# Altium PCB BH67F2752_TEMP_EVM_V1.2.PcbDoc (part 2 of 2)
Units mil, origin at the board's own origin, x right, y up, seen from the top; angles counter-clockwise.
Board outline 4690.02 x 3082.03 mil, 2 copper layers (Top Layer, Bottom Layer); 69 components, 83 nets, 365 pads, 122 vias.
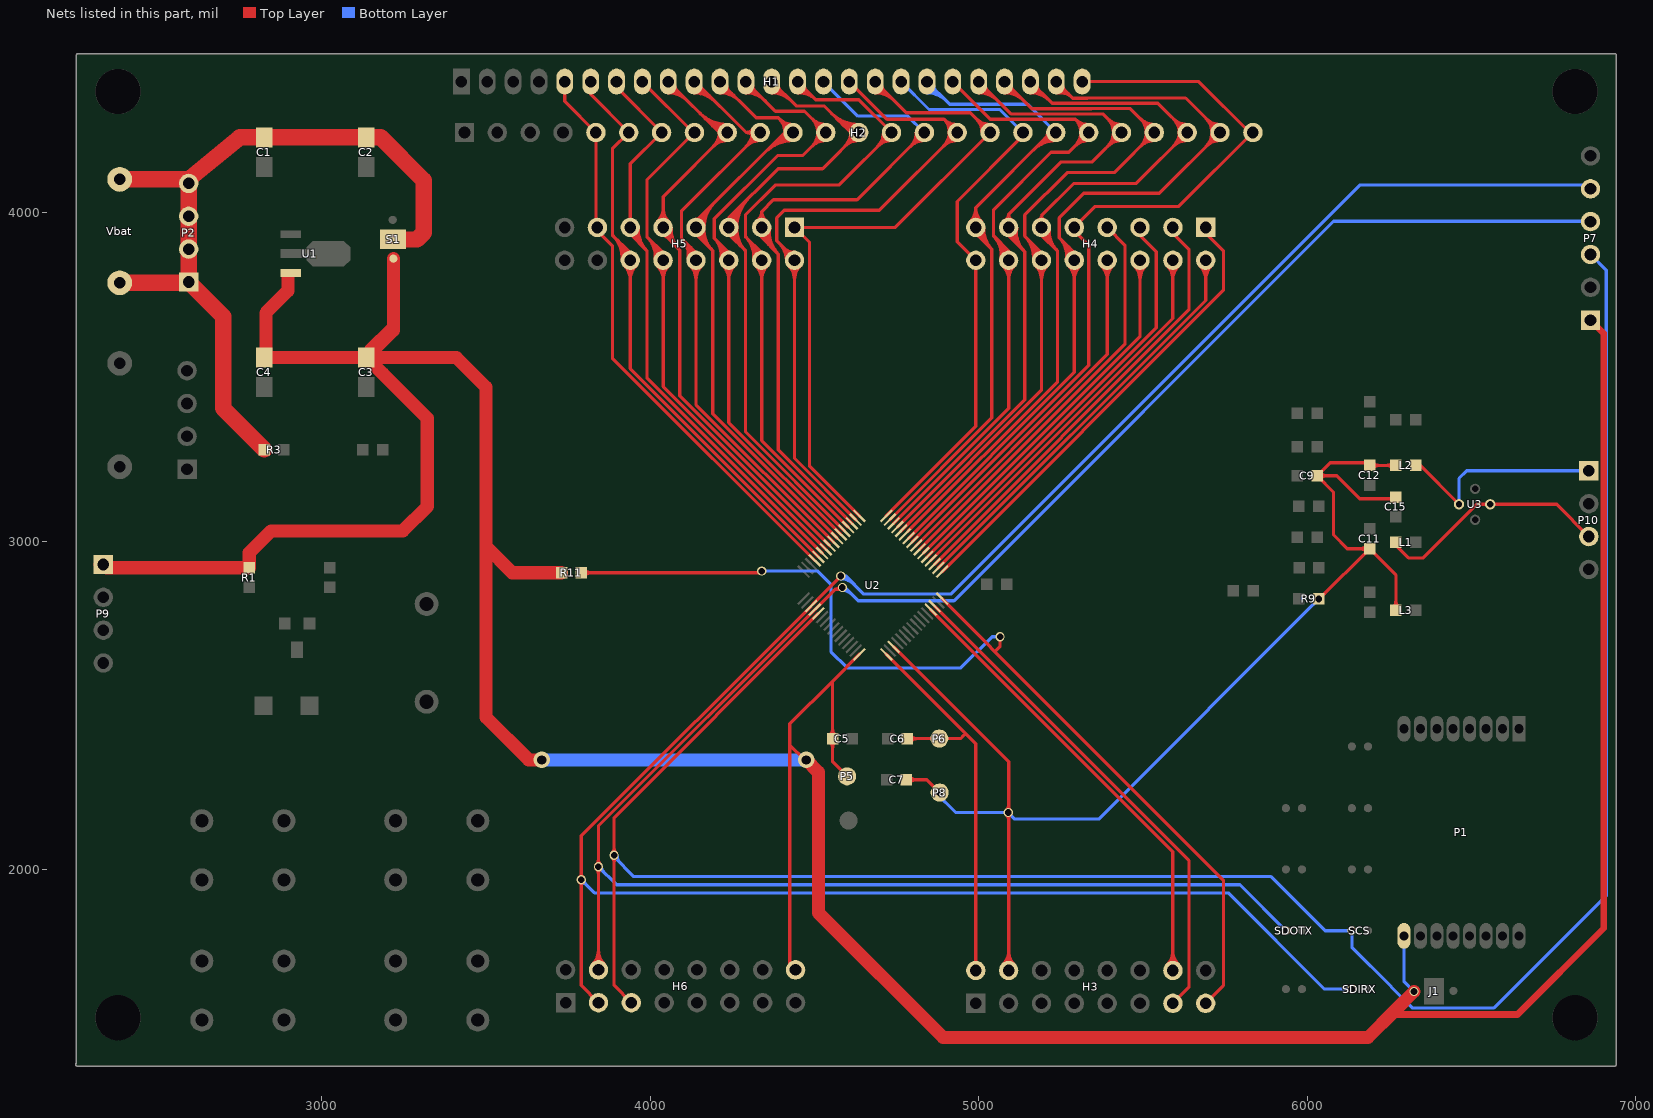
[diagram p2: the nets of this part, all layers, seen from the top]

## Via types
v1: diameter 28, hole 20, Top Layer to Bottom Layer, tented top, 64 vias
v2: diameter 28, hole 16, Top Layer to Bottom Layer, tented top, 56 vias
v3: diameter 50, hole 28, Top Layer to Bottom Layer, tented top, 2 vias

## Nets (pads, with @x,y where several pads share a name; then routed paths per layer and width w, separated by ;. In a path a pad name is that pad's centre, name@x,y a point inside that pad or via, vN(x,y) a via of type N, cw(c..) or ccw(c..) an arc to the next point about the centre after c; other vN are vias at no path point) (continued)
SCSB: H6.5 P7.3 SCS.1 U2.53 | length 6918.2
  Top Layer w10: v1@3883.64,2038.64 cw(c3868.27,2023.27) 3890,2023.27 cw(c3911.73,2023.27) v1@3896.36,2038.64 ; v1@3883.64,2051.36 ccw(c3868.27,2066.73) 3890,2066.73 ccw(c3911.73,2066.73) v1@3896.36,2051.36 ; H6.5@3942.38,1596 3890,1648.37 v1(3890,2045) 3890,2158.86 U2.53@4512.06,2780.92
  Bottom Layer w10: v1(3890,2045) 3890,2040 3950,1980 5890,1980 6054.67,1815.33 v1(6136.05,1815.33) 6136.05,1765 6255,1646.05 6255,1645 6320,1580 6568.71,1580 6910,1921.29 6910,3826.06 P7.3@6862.36,3873.7 ; v1@3899,2045 ccw(c3932.8,2045) 3908.9,2021.1
"SDI RX": H6.3 P7.5 SDIRX.1 U2.51 | length 7143.1
  Top Layer w10: v1@3783.64,1963.64 cw(c3768.27,1948.27) 3790,1948.27 cw(c3811.73,1948.27) v1@3796.36,1963.64 ; v1@3783.64,1976.36 ccw(c3768.27,1991.73) 3790,1991.73 ccw(c3811.73,1991.73) v1@3796.36,1976.36 ; H6.3@3842.38,1596 3790,1648.37 v1(3790,1970) 3790,2104.11 U2.51@4489.43,2803.54 ; U2.51@4494.12,2808.23 4579.94,2894.05 v1(4579.94,2895)
  Bottom Layer w10: v1@3790,1961 cw(c3790,1939.27) 3805.36,1954.64 cw(c3820.73,1970) v1@3799,1970 ; v1(3790,1970) 3830,1930 5760,1930 6052.59,1637.41 v1(6136.05,1637.41) ; v1@4579.94,2886 cw(c4579.94,2827.92) 4621.01,2868.99 ; v1(4579.94,2895) 4595,2895 ; v1@4579.94,2896 cw(c4579.94,2862.06) 4603.94,2886.06 ; v1@4587.87,2890.74 cw(c4595,2886.9) 4595,2895 ; v1@4587.87,2899.26 ccw(c4595,2903.1) 4595,2895 ; P7.5@6867.36,4085 6160,4085 4915,2840 4650,2840 4595,2895
"SDO TX": H6.4 P7.4 SDOTX.1 U2.52 | length 6740
  Top Layer w10: H6.4@3825.03,1713.34 ccw(c3783.16,1755.21) 3842.38,1755.21 ccw(c3901.59,1755.21) H6.4@3859.72,1713.34 ; H6.4@3832.1,1706.27 ccw(c3807.3,1731.07) 3842.38,1731.07 ccw(c3877.45,1731.07) H6.4@3852.65,1706.27 ; v1@3836.01,2003.64 cw(c3820.65,1988.27) 3842.38,1988.27 cw(c3864.1,1988.27) v1@3848.74,2003.64 ; v1@3836.01,2016.36 ccw(c3820.65,2031.73) 3842.38,2031.73 ccw(c3864.1,2031.73) v1@3848.74,2016.36 ; H6.4@3842.38,1696 v1(3842.38,2010) 3842.38,2133.86 U2.52@4500.75,2792.23 4563.52,2855 ; v1@4576.77,2863.63 cw(c4563.52,2869.48) 4563.52,2855 ; v1(4585,2860) 4585,2855 4563.52,2855
  Bottom Layer w10: v1@3842.38,2001 cw(c3842.38,1979.27) 3857.74,1994.64 cw(c3873.1,2010) v1@3851.38,2010 ; v1(3842.38,2010) 3897.38,1955 5795.31,1955 v1(5934.97,1815.33) ; v1@4585,2851 cw(c4585,2810.48) 4613.65,2839.13 ; v1(4585,2860) 4592.78,2860 4632.78,2820 4925,2820 6080,3975 6852.36,3975 P7.4@6867.36,3990
SEG0: H1.5 H2.5 H5.13 U2.45 | length 1766.4
  Top Layer w10: H1.5@3739.96,4400 3739.96,4339.61 H2.5@3834.57,4245 H5.13@3834.57,3960.63 ; H5.13@3839.2,3956 3839.2,3945.8 3885,3900 3885,3557.88 U2.45@4500.75,2942.14
SEG1: H1.6 H2.6 H5.12 U2.44 | length 2122.1
  Top Layer w10: H1.6@3818.7,4400 3818.7,4360.87 H2.6@3934.57,4245 3885,4195.43 3885,3932.82 ; 3901.17,3916.66 cw(c3844.25,3859.74) H5.12@3924.68,3856.57 ; H5.12@3914.69,3856.97 ccw(c3813.14,3860.96) 3885,3932.82 ; 3917.33,3900.49 cw(c3875.35,3858.51) H5.12@3934.67,3856.18 ; H5.12@3921.85,3838.66 cw(c3879.98,3796.79) 3939.2,3796.79 cw(c3998.41,3796.79) H5.12@3956.54,3838.66 ; H5.12@3928.92,3845.73 cw(c3904.12,3820.93) 3939.2,3820.93 cw(c3974.27,3820.93) H5.12@3949.47,3845.73 ; U2.44@4512.06,2953.45 3939.2,3526.31 H5.12@3939.2,3856 3939.2,3878.63 3885,3932.82
SEG2: H1.7 H2.7 H5.11 U2.43 | length 1952.7
  Top Layer w10: H1.7@3897.44,4400 3897.44,4382.13 H2.7@4034.57,4245 3939.2,4149.63 H5.11@3939.2,3956 3939.2,3936 3990,3885.2 ; H5.11@3943.72,3955.73 ccw(c3994.59,3952.68) 3958.55,3916.65 ; H5.11@3953.7,3955.13 ccw(c4024.25,3950.9) 3974.27,3900.92 ; H5.11@3963.68,3954.53 ccw(c4053.92,3949.12) 3990,3885.2 ; U2.43@4523.37,2964.76 3990,3498.14 3990,3885.2
SEG3: H1.8 H2.8 H5.10 U2.42 | length 2107.7
  Top Layer w10: H1.8@3976.18,4400 4131.18,4245 H2.8@4134.57,4245 3990,4100.43 3990,3927.82 ; 4004.93,3912.89 cw(c3956.29,3864.25) H5.10@4024.74,3857.44 ; H5.10@4014.79,3858.43 ccw(c3929.14,3866.96) 3990,3927.82 ; 4019.86,3897.96 cw(c3983.45,3861.55) H5.10@4034.69,3856.45 ; H5.10@4021.85,3838.66 cw(c3979.98,3796.79) 4039.2,3796.79 cw(c4098.41,3796.79) H5.10@4056.54,3838.66 ; H5.10@4028.92,3845.73 cw(c4004.12,3820.93) 4039.2,3820.93 cw(c4074.27,3820.93) H5.10@4049.47,3845.73 ; U2.42@4534.69,2976.08 4039.2,3471.57 H5.10@4039.2,3856 4039.2,3878.63 3990,3927.82
SEG4: H1.9 H2.9 H5.9 U2.41 | length 2684.5
  Top Layer w10: H5.9@4021.85,3973.34 ccw(c3979.98,4015.21) 4039.2,4015.21 ccw(c4098.41,4015.21) H5.9@4056.54,3973.34 ; H5.9@4028.92,3966.27 ccw(c4004.12,3991.07) 4039.2,3991.07 ccw(c4074.27,3991.07) H5.9@4049.47,3966.27 ; H5.9@4039.2,3931.47 cw(c4039.2,3916.19) 4050,3927 ; H5.9@4043.72,3955.79 ccw(c4092.47,3953.55) 4057.96,3919.04 ; H5.9@4053.71,3955.33 ccw(c4123.09,3952.13) 4073.98,3903.02 ; H1.9@4054.92,4365.63 cw(c4054.92,4282.65) 4113.59,4341.33 ; H1.9@4054.92,4375.63 cw(c4054.92,4316.8) 4096.52,4358.4 ; H1.9@4054.92,4385.63 cw(c4054.92,4350.94) 4079.45,4375.47 ; H1.9@4054.92,4400 4209.92,4245 H2.9@4234.57,4245 4039.2,4049.63 H5.9@4039.2,3956 4039.2,3937.8 4090,3887 ; H5.9@4063.7,3954.87 ccw(c4153.72,3950.72) 4090,3887 ; H1.9@4075.51,4386.22 ccw(c4091.95,4386.22) 4080.33,4374.59 ; 4150.62,4304.3 ccw(c4234.57,4388.24) H2.9@4234.57,4269.53 ; 4167.69,4287.23 ccw(c4234.57,4354.1) H2.9@4234.57,4259.53 ; 4184.76,4270.16 ccw(c4234.57,4319.96) H2.9@4234.57,4249.53 ; 4201.84,4253.09 ccw(c4234.57,4285.82) H2.9@4234.57,4239.53 ; H2.9@4210.04,4245 cw(c4150.82,4245) 4192.7,4203.13 cw(c4234.57,4161.26) H2.9@4234.57,4220.47 ; H2.9@4220.04,4245 cw(c4184.97,4245) 4209.77,4220.2 cw(c4234.57,4195.4) H2.9@4234.57,4230.47 ; U2.41@4546,2987.39 4090,3443.39 4090,3887
SEG5: H1.10 H2.10 H5.8 U2.40 | length 2473
  Top Layer w10: 4108.7,3909.13 cw(c4067.68,3868.11) H5.8@4124.87,3858.43 ; H5.8@4115.01,3860.1 ccw(c4044.26,3872.08) 4095,3922.82 ; H5.8@4121.85,3838.66 cw(c4079.98,3796.79) 4139.2,3796.79 cw(c4198.41,3796.79) H5.8@4156.54,3838.66 ; 4122.4,3895.43 cw(c4091.11,3864.14) H5.8@4134.73,3856.76 ; H5.8@4128.92,3845.73 cw(c4104.12,3820.93) 4139.2,3820.93 cw(c4174.27,3820.93) H5.8@4149.47,3845.73 ; H1.10@4133.66,4365.63 cw(c4133.66,4274.88) 4197.83,4339.05 ; H1.10@4133.66,4375.63 cw(c4133.66,4309.02) 4180.76,4356.12 ; H1.10@4133.66,4385.63 cw(c4133.66,4343.16) 4163.69,4373.19 ; H1.10@4133.66,4400 4136.88,4400 4291.88,4245 ; H2.10@4310.04,4245 cw(c4250.82,4245) 4292.7,4203.13 cw(c4334.57,4161.26) H2.10@4334.57,4220.47 ; H2.10@4313.38,4232.65 ccw(c4291.88,4220.12) 4291.88,4245 ; H2.10@4313.38,4257.35 cw(c4291.88,4269.88) 4291.88,4245 ; H2.10@4320.04,4245 cw(c4284.97,4245) 4309.77,4220.2 cw(c4334.57,4195.4) H2.10@4334.57,4230.47 ; U2.40@4557.32,2998.7 4139.2,3416.82 H5.8@4139.2,3856 4139.2,3878.63 4095,3922.82 ; 4095,3922.82 4095,4005.43 H2.10@4334.57,4245 4291.88,4245
SEG6: H1.11 H2.11 H5.7 U2.39 | length 2771.6
  Top Layer w10: H5.7@4139.2,3980.53 ccw(c4139.2,3995.81) 4150,3985 ; H5.7@4143.72,3955.73 ccw(c4194.59,3952.68) 4158.55,3916.65 ; H5.7@4143.72,3956 cw(c4198.59,3956) 4159.79,3994.79 ; H5.7@4153.7,3955.13 ccw(c4224.25,3950.9) 4174.27,3900.92 ; H5.7@4153.72,3956 cw(c4232.73,3956) 4176.86,4011.86 ; H5.7@4163.68,3954.53 ccw(c4253.92,3949.12) 4190,3885.2 ; H5.7@4163.72,3956 cw(c4266.87,3956) 4193.94,4028.94 ; H1.11@4212.4,4365.63 cw(c4212.4,4282.65) 4271.07,4341.33 ; H1.11@4212.4,4375.63 cw(c4212.4,4316.8) 4254,4358.4 ; H1.11@4212.4,4385.63 cw(c4212.4,4350.94) 4236.93,4375.47 ; H1.11@4212.4,4400 4322.4,4290 4389.57,4290 H2.11@4434.57,4245 4410,4245 4139.2,3974.2 H5.7@4139.2,3956 4139.2,3936 4190,3885.2 ; H1.11@4232.99,4386.22 ccw(c4249.43,4386.22) 4237.81,4374.59 ; 4350.76,4185.76 cw(c4434.57,4101.95) H2.11@4434.57,4220.47 ; 4367.83,4202.83 cw(c4434.57,4136.09) H2.11@4434.57,4230.47 ; 4384.9,4219.9 cw(c4434.57,4170.23) H2.11@4434.57,4240.47 ; 4401.97,4236.97 cw(c4434.57,4204.37) H2.11@4434.57,4250.47 ; H2.11@4410.04,4245 ccw(c4350.82,4245) 4392.7,4286.87 ccw(c4434.57,4328.74) H2.11@4434.57,4269.53 ; H2.11@4420.04,4245 ccw(c4384.97,4245) 4409.77,4269.8 ccw(c4434.57,4294.6) H2.11@4434.57,4259.53 ; U2.39@4568.63,3010.02 4190,3388.65 4190,3885.2
SEG7: H1.12 H2.12 H5.6 U2.38 | length 2638.2
  Top Layer w10: 4208.7,3909.13 cw(c4167.68,3868.11) H5.6@4224.87,3858.43 ; H5.6@4215.01,3860.1 ccw(c4144.26,3872.08) 4195,3922.82 ; H5.6@4221.85,3838.66 cw(c4179.98,3796.79) 4239.2,3796.79 cw(c4298.41,3796.79) H5.6@4256.54,3838.66 ; 4222.4,3895.43 cw(c4191.11,3864.14) H5.6@4234.73,3856.76 ; H5.6@4228.92,3845.73 cw(c4204.12,3820.93) 4239.2,3820.93 cw(c4274.27,3820.93) H5.6@4249.47,3845.73 ; H1.12@4291.14,4365.63 cw(c4291.14,4282.65) 4349.81,4341.33 ; H1.12@4291.14,4375.63 cw(c4291.14,4316.8) 4332.74,4358.4 ; H1.12@4291.14,4385.63 cw(c4291.14,4350.94) 4315.67,4375.47 ; H1.12@4291.14,4400 4381.14,4310 4469.57,4310 H2.12@4534.57,4245 4464.57,4175 4387.52,4175 4195,3982.48 4195,3922.82 ; H1.12@4311.73,4386.22 ccw(c4328.17,4386.22) 4316.55,4374.59 ; H2.12@4534.57,4220.47 ccw(c4534.57,4161.26) 4492.7,4203.13 ccw(c4450.82,4245) 4510.04,4245 ccw(c4450.82,4245) 4492.7,4286.87 ccw(c4534.57,4328.74) H2.12@4534.57,4269.53 ; H2.12@4534.57,4230.47 ccw(c4534.57,4195.4) 4509.77,4220.2 ccw(c4484.97,4245) 4520.04,4245 ccw(c4484.97,4245) 4509.77,4269.8 ccw(c4534.57,4294.6) H2.12@4534.57,4259.53 ; U2.38@4579.94,3021.33 4239.2,3362.08 H5.6@4239.2,3856 4239.2,3878.63 4195,3922.82
SEG8: H1.13 H2.13 H5.5 U2.37 | length 2960.5
  Top Layer w10: H5.5@4233.72,3956 cw(c4290.53,3956) 4250.36,3996.16 ; H5.5@4243.72,3955.72 ccw(c4294.81,3952.58) 4258.61,3916.39 ; H5.5@4243.72,3956 cw(c4324.67,3956) 4267.43,4013.23 ; H5.5@4253.7,3955.11 ccw(c4324.38,3950.77) 4274.31,3900.69 ; H5.5@4253.72,3956 cw(c4358.81,3956) 4284.5,4030.31 ; H5.5@4263.68,3954.5 ccw(c4353.95,3948.95) 4290,3885 ; H5.5@4263.72,3956 cw(c4392.95,3956) 4301.57,4047.38 ; H1.13@4369.88,4365.63 cw(c4369.88,4282.65) 4428.55,4341.33 ; H1.13@4369.88,4375.63 cw(c4369.88,4316.8) 4411.48,4358.4 ; H1.13@4369.88,4385.63 cw(c4369.88,4350.94) 4394.41,4375.47 ; H1.13@4369.88,4400 4443.88,4326 4529,4326 4610,4245 H2.13@4634.57,4245 4524.57,4135 4389.2,4135 4239.2,3985 H5.5@4239.2,3956 4239.2,3935.8 4290,3885 ; H1.13@4390.47,4386.22 ccw(c4406.91,4386.22) 4395.29,4374.59 ; 4550.76,4304.24 ccw(c4634.57,4388.05) H2.13@4634.57,4269.53 ; 4567.83,4287.17 ccw(c4634.57,4353.91) H2.13@4634.57,4259.53 ; 4584.9,4270.1 ccw(c4634.57,4319.77) H2.13@4634.57,4249.53 ; U2.37@4591.26,3032.65 4290,3333.9 4290,3885 ; 4601.97,4253.03 ccw(c4634.57,4285.63) H2.13@4634.57,4239.53 ; H2.13@4610.04,4245 cw(c4550.82,4245) 4592.7,4203.13 cw(c4634.57,4161.26) H2.13@4634.57,4220.47 ; H2.13@4620.04,4245 cw(c4584.97,4245) 4609.77,4220.2 cw(c4634.57,4195.4) H2.13@4634.57,4230.47
SEG9: H1.14 H2.14 H5.4 U2.36 | length 2572.4
  Top Layer w10: 4304.93,3912.89 cw(c4256.29,3864.25) H5.4@4324.74,3857.44 ; H5.4@4314.79,3858.43 ccw(c4229.14,3866.96) 4290,3927.82 ; 4319.86,3897.96 cw(c4283.45,3861.55) H5.4@4334.69,3856.45 ; H5.4@4321.85,3838.66 cw(c4279.98,3796.79) 4339.2,3796.79 cw(c4398.41,3796.79) H5.4@4356.54,3838.66 ; H5.4@4328.92,3845.73 cw(c4304.12,3820.93) 4339.2,3820.93 cw(c4374.27,3820.93) H5.4@4349.47,3845.73 ; H1.14@4448.62,4400 4503.62,4345 ; H1.14@4449.19,4375.65 cw(c4451.9,4325) 4487.76,4360.86 ; H1.14@4449.72,4365.66 cw(c4453.51,4294.89) 4503.62,4345 ; H1.14@4469.21,4386.22 ccw(c4485.66,4386.22) 4474.03,4374.59 ; U2.36@4602.57,3043.96 4339.2,3307.33 H5.4@4339.2,3856 4339.2,3878.63 4290,3927.82 ; H2.14@4710.04,4245 cw(c4650.82,4245) 4692.7,4203.13 cw(c4734.57,4161.26) H2.14@4734.57,4220.47 ; H2.14@4720.04,4245 cw(c4684.97,4245) 4709.77,4220.2 cw(c4734.57,4195.4) H2.14@4734.57,4230.47 ; 4290,3927.82 4290,3995 4380,4085 4574.57,4085 H2.14@4734.57,4245 4634.57,4345 4503.62,4345
SEG10: H1.15 H2.15 H5.3 U2.35 | length 2515.4
  Top Layer w10: H5.3@4324.76,3975.83 ccw(c4304.11,4004.2) 4339.2,4004.2 ; H5.3@4333.77,3956.71 ccw(c4379.56,3950.74) 4346.91,3918.09 ; H5.3@4334.17,3931.99 cw(c4332.87,3925.8) 4339.2,3925.8 ; H5.3@4343.69,3955.42 ccw(c4404.97,3947.43) 4361.27,3903.73 ; H5.3@4344.23,3931.99 ccw(c4345.52,3925.8) 4339.2,3925.8 ; H5.3@4353.6,3954.12 ccw(c4430.39,3944.12) 4375.63,3889.37 ; H5.3@4353.63,3975.83 cw(c4374.28,4004.2) 4339.2,4004.2 ; H5.3@4363.52,3952.83 ccw(c4455.8,3940.81) 4390,3875 ; U2.35@4613.88,3055.27 4390,3279.16 4390,3875 ; H2.15@4810.04,4245 cw(c4750.82,4245) 4792.7,4203.13 cw(c4834.57,4161.26) H2.15@4834.57,4220.47 ; H2.15@4820.04,4245 cw(c4784.97,4245) 4809.77,4220.2 cw(c4834.57,4195.4) H2.15@4834.57,4230.47 ; H2.15@4834.57,4245 4629.57,4040 4375,4040 4339.2,4004.2 ; 4339.2,3925.8 4390,3875 ; 4339.2,3925.8 H5.3@4339.2,3956 4339.2,4004.2
  Bottom Layer w10: H1.15@4527.36,4400 4632.36,4295 4784.57,4295 H2.15@4834.57,4245
SEG11: H1.16 H2.16 H5.2 U2.34 | length 2631.7
  Top Layer w10: 4393.93,3906.07 cw(c4343.86,3856) H5.2@4414.67,3856 ; 4405.52,3894.48 ccw(c4439.2,3928.15) H5.2@4439.2,3880.53 ; 4411,3889 cw(c4378,3856) H5.2@4424.67,3856 ; H5.2@4421.85,3838.66 cw(c4379.98,3796.79) 4439.2,3796.79 cw(c4498.41,3796.79) H5.2@4456.54,3838.66 ; H5.2@4428.92,3845.73 cw(c4404.12,3820.93) 4439.2,3820.93 cw(c4474.27,3820.93) H5.2@4449.47,3845.73 ; H1.16@4606.1,4400 4720.57,4285.53 4851.35,4285.53 4851.88,4285 4894.57,4285 ; U2.34@4625.2,3066.59 4439.2,3252.59 H5.2@4439.2,3856 4439.2,3860.8 4385,3915 4385,3985 4407.92,4007.92 4697.49,4007.92 H2.16@4934.57,4245 4894.57,4285 ; H2.16@4910.04,4245 cw(c4850.82,4245) 4892.7,4203.13 cw(c4934.57,4161.26) H2.16@4934.57,4220.47 ; H2.16@4910.05,4245.81 ccw(c4857.12,4247.55) 4894.57,4285 ; H2.16@4920.04,4245 cw(c4884.97,4245) 4909.77,4220.2 cw(c4934.57,4195.4) H2.16@4934.57,4230.47 ; H2.16@4920.05,4245.48 ccw(c4888.69,4246.51) 4910.88,4268.69 ccw(c4933.06,4290.87) H2.16@4934.09,4259.52 ; H2.16@4933.76,4269.51 cw(c4932.02,4322.45) 4894.57,4285
SEG12: H1.17 H2.17 H5.1 U2.33 | length 2388.5
  Top Layer w10: U2.33@4636.51,3077.9 4485,3229.41 4485,3910.2 H5.1@4439.2,3956 4745.57,3956 H2.17@5034.57,4245 4974.57,4305 4779.84,4305 H1.17@4684.84,4400 ; H1.17@4684.84,4365.63 cw(c4684.84,4282.65) 4743.52,4341.33 ; H1.17@4684.84,4375.63 cw(c4684.84,4316.8) 4726.44,4358.4 ; H1.17@4684.84,4385.63 cw(c4684.84,4350.94) 4709.37,4375.47 ; H1.17@4705.43,4386.22 ccw(c4721.88,4386.22) 4710.25,4374.59 ; H2.17@5010.04,4245 ccw(c4950.82,4245) 4992.7,4286.87 ccw(c5034.57,4328.74) H2.17@5034.57,4269.53 ; H2.17@5020.04,4245 ccw(c4984.97,4245) 5009.77,4269.8 ccw(c5034.57,4294.6) H2.17@5034.57,4259.53
SEG13: H1.18 H2.18 H4.16 U2.32 | length 1821
  Top Layer w10: U2.32@4718.54,3077.9 4991,3350.36 H4.16@4991,3856 4935,3912 4935,4035 5134.57,4234.57 H2.18@5134.57,4245
  Bottom Layer w10: H1.18@4763.58,4400 4848.58,4315 5064.57,4315 H2.18@5134.57,4245
SEG14: H1.19 H2.19 H4.15 U2.31 | length 2556.6
  Top Layer w10: U2.31@4729.85,3066.59 5040,3376.74 5040,3890 ; H4.15@4973.66,3973.34 ccw(c4931.79,4015.21) 4991,4015.21 ccw(c5050.21,4015.21) H4.15@5008.34,3973.34 ; H4.15@4980.73,3966.27 ccw(c4955.93,3991.07) 4991,3991.07 ccw(c5026.07,3991.07) H4.15@5001.27,3966.27 ; H4.15@4991,3931.47 cw(c4991,3913.3) 5003.85,3926.15 ; H4.15@4995.52,3955.73 ccw(c5040.14,3953.08) 5008.53,3921.47 ; H4.15@5005.5,3955.14 ccw(c5069.84,3951.31) 5024.26,3905.74 ; H4.15@5015.48,3954.54 ccw(c5099.53,3949.54) 5040,3890 ; 5167.09,4192.52 cw(c5234.57,4125.04) H2.19@5234.57,4220.47 ; 5184.16,4209.59 cw(c5234.57,4159.19) H2.19@5234.57,4230.47 ; 5201.23,4226.66 cw(c5234.57,4193.33) H2.19@5234.57,4240.47 ; 5203.3,4228.74 ccw(c5187.04,4245) H2.19@5210.04,4245 ; H2.19@5234.57,4245 5219.57,4245 4991,4016.43 H4.15@4991,3956 4991,3939 5040,3890
  Bottom Layer w10: H1.19@4842.32,4365.63 cw(c4842.32,4282.65) 4901,4341.33 ; H1.19@4842.32,4375.63 cw(c4842.32,4316.8) 4883.92,4358.4 ; H1.19@4842.32,4385.63 cw(c4842.32,4350.94) 4866.85,4375.47 ; H1.19@4842.32,4400 4911.32,4331 5148.57,4331 H2.19@5234.57,4245 ; H1.19@4862.91,4386.22 ccw(c4879.36,4386.22) 4867.73,4374.59
SEG15: H1.20 H2.20 H4.14 U2.30 | length 2647.6
  Top Layer w10: U2.30@4741.16,3055.27 5091,3405.11 H4.14@5091,3856 5091,3884 5045,3930 ; H1.20@4921.06,4400 5035.43,4285.63 5293.94,4285.63 ; 5058.54,3916.46 cw(c5012.21,3870.13) H4.14@5076.7,3858.56 ; H4.14@5066.86,3860.33 ccw(c4989.25,3874.25) 5045,3930 ; 5072.07,3902.93 cw(c5035.16,3866.01) H4.14@5086.54,3856.8 ; H4.14@5073.66,3838.66 cw(c5031.79,3796.79) 5091,3796.79 cw(c5150.21,3796.79) H4.14@5108.34,3838.66 ; H4.14@5080.73,3845.73 cw(c5055.93,3820.93) 5091,3820.93 cw(c5126.07,3820.93) H4.14@5101.27,3845.73 ; 5085.61,3889.39 cw(c5058.11,3861.9) H4.14@5096.39,3855.03 ; H2.20@5310.04,4245 cw(c5250.82,4245) 5292.7,4203.13 cw(c5334.57,4161.26) H2.20@5334.57,4220.47 ; H2.20@5310.05,4245.53 ccw(c5255.02,4246.71) 5293.94,4285.63 ; H2.20@5320.04,4245 cw(c5284.97,4245) 5309.77,4220.2 cw(c5334.57,4195.4) H2.20@5334.57,4230.47 ; H2.20@5320.04,4245.31 ccw(c5287.45,4246.01) 5310.5,4269.06 ccw(c5333.55,4292.11) H2.20@5334.25,4259.52 ; H2.20@5334.04,4269.52 cw(c5332.85,4324.54) 5293.94,4285.63 ; 5045,3930 5045,4010 5220,4185 5274.57,4185 H2.20@5334.57,4245 5293.94,4285.63
SEG16: H1.21 H2.21 H4.13 U2.29 | length 2794.6
  Top Layer w10: U2.29@4752.48,3043.96 5140,3431.48 5140,3882 ; H1.21@4999.8,4365.63 cw(c4999.8,4282.65) 5058.48,4341.33 ; H1.21@4999.8,4375.63 cw(c4999.8,4316.8) 5041.4,4358.4 ; H1.21@4999.8,4385.63 cw(c4999.8,4350.94) 5024.33,4375.47 ; H1.21@4999.8,4400 5098.17,4301.63 5377.94,4301.63 H2.21@5434.57,4245 5344.57,4155 5250,4155 5091,3996 ; H1.21@5020.39,4386.22 ccw(c5036.84,4386.22) 5025.21,4374.59 ; H4.13@5079.88,3977.86 ccw(c5070.65,3996) 5091,3996 ; H4.13@5085.57,3956.65 ccw(c5122.79,3952.22) 5096.28,3925.72 ; H4.13@5095.5,3955.47 ccw(c5148.84,3949.13) 5110.86,3911.14 ; H4.13@5102.12,3977.86 cw(c5111.35,3996) 5091,3996 ; H4.13@5105.43,3954.29 ccw(c5174.89,3946.04) 5125.43,3896.57 ; H4.13@5115.36,3953.11 ccw(c5200.94,3942.94) 5140,3882 ; H2.21@5434.57,4220.47 ccw(c5434.57,4161.26) 5392.7,4203.13 ccw(c5350.82,4245) 5410.04,4245 ccw(c5350.82,4245) 5392.7,4286.87 ccw(c5434.57,4328.74) H2.21@5434.57,4269.53 ; H2.21@5434.57,4230.47 ccw(c5434.57,4195.4) 5409.77,4220.2 ccw(c5384.97,4245) 5420.04,4245 ccw(c5384.97,4245) 5409.77,4269.8 ccw(c5434.57,4294.6) H2.21@5434.57,4259.53 ; 5091,3996 H4.13@5091,3956 5091,3931 5140,3882
SEG17: H1.22 H2.22 H4.12 U2.28 | length 2962.9
  Top Layer w10: U2.28@4763.79,3032.65 5191,3459.85 H4.12@5191,3856 5191,3878.63 5140,3929.63 5140,3993.98 5269.02,4123 5412.57,4123 H2.22@5534.57,4245 5461.57,4318 5343.54,4318 5343.17,4317.63 5160.91,4317.63 H1.22@5078.54,4400 ; H1.22@5078.54,4365.63 cw(c5078.54,4282.65) 5137.22,4341.33 ; H1.22@5078.54,4375.63 cw(c5078.54,4316.8) 5120.14,4358.4 ; H1.22@5078.54,4385.63 cw(c5078.54,4350.94) 5103.07,4375.47 ; H1.22@5099.13,4386.22 ccw(c5115.58,4386.22) 5103.95,4374.59 ; 5140,3929.62 cw(c5075.27,3864.9) H4.12@5166.54,3857.88 ; 5155.38,3914.25 cw(c5103.83,3862.7) H4.12@5176.52,3857.11 ; 5170.75,3898.87 cw(c5132.38,3860.51) H4.12@5186.49,3856.35 ; H4.12@5173.66,3838.66 cw(c5131.79,3796.79) 5191,3796.79 cw(c5250.21,3796.79) H4.12@5208.34,3838.66 ; H4.12@5180.73,3845.73 cw(c5155.93,3820.93) 5191,3820.93 cw(c5226.07,3820.93) H4.12@5201.27,3845.73 ; H2.22@5534.57,4220.47 ccw(c5534.57,4161.26) 5492.7,4203.13 ccw(c5450.82,4245) 5510.04,4245 ccw(c5450.82,4245) 5492.7,4286.87 ccw(c5534.57,4328.74) H2.22@5534.57,4269.53 ; H2.22@5534.57,4230.47 ccw(c5534.57,4195.4) 5509.77,4220.2 ccw(c5484.97,4245) 5520.04,4245 ccw(c5484.97,4245) 5509.77,4269.8 ccw(c5534.57,4294.6) H2.22@5534.57,4259.53
SEG18: H1.23 H2.23 H4.11 U2.27 | length 2923
  Top Layer w10: U2.27@4784.39,3030.61 5240,3486.23 5240,3883.65 ; H1.23@5157.28,4365.63 cw(c5157.28,4282.65) 5215.96,4341.33 ; H1.23@5157.28,4375.63 cw(c5157.28,4316.8) 5198.88,4358.4 ; H1.23@5157.28,4385.63 cw(c5157.28,4350.94) 5181.81,4375.47 ; H1.23@5157.28,4400 5223.65,4333.63 5336.55,4333.63 5336.92,4334 5545.57,4334 H2.23@5634.57,4245 5479.57,4090 5290,4090 5191,3991 ; H1.23@5177.87,4386.22 ccw(c5194.32,4386.22) 5182.69,4374.59 ; H4.11@5182.63,3979.06 ccw(c5178.29,3991) 5191,3991 ; H4.11@5195.5,3955.52 ccw(c5247.18,3949.98) 5210.43,3913.22 ; H4.11@5199.37,3979.06 cw(c5203.71,3991) 5191,3991 ; H4.11@5205.44,3954.45 ccw(c5273.88,3947.11) 5225.21,3898.44 ; H4.11@5215.39,3953.38 ccw(c5300.59,3944.25) 5240,3883.66 ; H2.23@5634.57,4220.47 ccw(c5634.57,4161.26) 5592.7,4203.13 ccw(c5550.82,4245) 5610.04,4245 ccw(c5550.82,4245) 5592.7,4286.87 ccw(c5634.57,4328.74) H2.23@5634.57,4269.53 ; H2.23@5634.57,4230.47 ccw(c5634.57,4195.4) 5609.77,4220.2 ccw(c5584.97,4245) 5620.04,4245 ccw(c5584.97,4245) 5609.77,4269.8 ccw(c5634.57,4294.6) H2.23@5634.57,4259.53 ; 5191,3991 H4.11@5191,3956 5191,3932.65 5240,3883.65
SEG19: H1.24 H2.24 H4.10 U2.26 | length 3083.7
  Top Layer w10: U2.26@4786.42,3010.02 5291,3514.6 H4.10@5291,3856 5291,3879 5245,3925 ; H1.24@5236.02,4400 5286.39,4349.63 ; H1.24@5237.41,4375.72 cw(c5242.82,4334.73) 5272.06,4363.97 ; H1.24@5238.72,4365.81 cw(c5246.16,4309.4) 5286.39,4349.63 ; H1.24@5256.61,4386.22 ccw(c5273.06,4386.22) 5261.43,4374.59 ; 5259.1,3910.9 cw(c5215.22,3867.03) H4.10@5276.62,3858.09 ; H4.10@5266.73,3859.53 ccw(c5190.62,3870.61) 5245,3925 ; 5273.19,3896.81 cw(c5239.83,3863.45) H4.10@5286.52,3856.65 ; H4.10@5273.66,3838.66 cw(c5231.79,3796.79) 5291,3796.79 cw(c5350.21,3796.79) H4.10@5308.34,3838.66 ; H4.10@5280.73,3845.73 cw(c5255.93,3820.93) 5291,3820.93 cw(c5326.07,3820.93) H4.10@5301.27,3845.73 ; H2.24@5734.57,4220.47 ccw(c5734.57,4161.26) 5692.7,4203.13 ccw(c5650.82,4245) 5710.04,4245 ccw(c5650.82,4245) 5692.7,4286.87 ccw(c5734.57,4328.74) H2.24@5734.57,4269.53 ; H2.24@5734.57,4230.47 ccw(c5734.57,4195.4) 5709.77,4220.2 ccw(c5684.97,4245) 5720.04,4245 ccw(c5684.97,4245) 5709.77,4269.8 ccw(c5734.57,4294.6) H2.24@5734.57,4259.53 ; 5245,3925 5245,3985 5320,4060 5549.57,4060 H2.24@5734.57,4245 5629.57,4350 5330.29,4350 5329.92,4349.63 5286.39,4349.63
SEG20: H1.25 H2.25 H4.9 U2.25 | length 2445.3
  Top Layer w10: U2.25@4797.73,2998.7 5335,3535.97 5335,3902 5291,3946 H4.9@5291,3956 5355,4020 5609.57,4020 H2.25@5834.57,4245 5825,4245 5670,4400 H1.25@5314.76,4400
SEG21: H4.8 U2.24 | length 1257.8
  Top Layer w10: U2.24@4809.05,2987.39 5391,3569.35 H4.8@5391,3856 ; H4.8@5373.66,3838.66 cw(c5331.79,3796.79) 5391,3796.79 cw(c5450.21,3796.79) H4.8@5408.34,3838.66 ; H4.8@5380.73,3845.73 cw(c5355.93,3820.93) 5391,3820.93 cw(c5426.07,3820.93) H4.8@5401.27,3845.73
SEG22: H4.7 U2.23 | length 1261
  Top Layer w10: U2.23@4820.36,2976.08 5445,3600.72 5445,3902 H4.7@5391,3956
SEG23: H4.6 U2.22 | length 1312.4
  Top Layer w10: U2.22@4831.67,2964.76 5491,3624.09 H4.6@5491,3856 ; H4.6@5473.66,3838.66 cw(c5431.79,3796.79) 5491,3796.79 cw(c5550.21,3796.79) H4.6@5508.34,3838.66 ; H4.6@5480.73,3845.73 cw(c5455.93,3820.93) 5491,3820.93 cw(c5526.07,3820.93) H4.6@5501.27,3845.73
SEG24: H4.5 U2.21 | length 1311.6
  Top Layer w10: U2.21@4842.99,2953.45 5540,3650.46 5540,3882 5491,3931 H4.5@5491,3956
SEG25: H4.4 U2.20 | length 1367.1
  Top Layer w10: U2.20@4854.3,2942.14 5591,3678.84 H4.4@5591,3856 ; H4.4@5573.66,3838.66 cw(c5531.79,3796.79) 5591,3796.79 cw(c5650.21,3796.79) H4.4@5608.34,3838.66 ; H4.4@5580.73,3845.73 cw(c5555.93,3820.93) 5591,3820.93 cw(c5626.07,3820.93) H4.4@5601.27,3845.73
SEG26: H4.3 U2.19 | length 1366.2
  Top Layer w10: U2.19@4865.61,2930.82 5640,3705.21 5640,3890 5591,3939 H4.3@5591,3956
SEG27: H4.2 U2.18 | length 1421.8
  Top Layer w10: U2.18@4876.93,2919.51 5691,3733.58 H4.2@5691,3856 ; H4.2@5673.66,3838.66 cw(c5631.79,3796.79) 5691,3796.79 cw(c5750.21,3796.79) H4.2@5708.34,3838.66 ; H4.2@5680.73,3845.73 cw(c5655.93,3820.93) 5691,3820.93 cw(c5726.07,3820.93) H4.2@5701.27,3845.73
SEG28: H4.1 U2.17 | length 1425.1
  Top Layer w10: U2.17@4888.24,2908.19 5745,3764.95 5745,3885 5691,3939 H4.1@5691,3956
SEG29: H3.16 R11.2 U2.16 | length 3265.8
  Top Layer w10: R11.2@3790,2905 4334.2,2905 v1(4339.2,2910) ; R11.2@3798.84,2896.16 cw(c3820.18,2874.82) 3820.18,2905 cw(c3820.18,2935.18) R11.2@3798.84,2913.84 ; U2.16@4888.24,2826.17 5024.01,2690.41 ; 5024.41,2690 5049.41,2665 ; v1(5065,2710) 5065,2680.59 5049.41,2665 ; H3.16@5691,1594 5745,1648 5745,1969.41 5049.41,2665
  Bottom Layer w10: v1@4340,2910 4510.36,2910 4550,2870.36 4550,2665 4600,2615 4945.65,2615 5040.65,2710 v1(5065,2710)
SEG30: H3.14 U2.14 | length 1550.6
  Top Layer w10: U2.14@4865.61,2803.54 5640,2029.16 5640,1643 H3.14@5591,1594
SEG31: H3.13 U2.13 | length 1551.5
  Top Layer w10: U2.13@4854.3,2792.23 5591,2055.53 H3.13@5591,1694 ; H3.13@5573.66,1711.34 ccw(c5531.79,1753.21) 5591,1753.21 ccw(c5650.21,1753.21) H3.13@5608.34,1711.34 ; H3.13@5580.73,1704.27 ccw(c5555.93,1729.07) 5591,1729.07 ccw(c5626.07,1729.07) H3.13@5601.27,1704.27
VBAT: C1.2 C2.1 P2.1 P2.2 P2.3 P2.4 R3.1 S1.2@3217.01,3920 Vbat.1 Vbat.2 | length 2405.1
  Top Layer w10: S1.2@3220,3910.2 S1.2@3229.16,3919.36
  Top Layer w50: Vbat.1@2385,3787.52 P2.1@2597.48,3787.52 ; Vbat.2@2385,4102.48 2595,4102.48 2750,4230 C1.2@2825,4230 C2.1@3135,4230 3180,4230 3310,4100 3310,3939.31 3290.06,3919.36 S1.2@3229.16,3919.36 ; P2.4@2595,4090 P2.3@2595,3990 P2.2@2595,3890 P2.1@2595,3790 P2.1@2597.48,3787.52 ; R3.1@2825,3280 2700,3405 2700,3685 P2.1@2597.48,3787.52
VCM: C7.2 C9.1 C11.1 C12.1 C15.1 H3.3 L2.2 L3.2 P8.1 R9.1 U2.3 | length 4631.2
  Top Layer w10: U2.3@4741.16,2679.09 5091,2329.25 v1@5091,2175 ; C7.2@4780,2275 4830,2275 4841.65,2275 P8.1@4881.14,2235.51 ; C7.2@4788.84,2266.16 cw(c4810.18,2244.82) 4810.18,2275 cw(c4810.18,2305.18) C7.2@4788.84,2283.84 ; P8.1@4863.47,2253.18 cw(c4845.29,2235) P8.1@4871,2235 ; P8.1@4867.45,2249.2 ccw(c4880,2261.74) P8.1@4880,2244 ; P8.1@4879.49,2235.51 v1(4880,2235) ; H3.3@5073.66,1711.34 ccw(c5031.79,1753.21) 5091,1753.21 ccw(c5150.21,1753.21) H3.3@5108.34,1711.34 ; H3.3@5080.73,1704.27 ccw(c5055.93,1729.07) 5091,1729.07 ccw(c5126.07,1729.07) H3.3@5101.27,1704.27 ; v1@5083.64,2168.64 cw(c5065.86,2150.86) 5091,2150.86 ; v1@5083.64,2181.36 ccw(c5065.86,2199.14) 5091,2199.14 ; H3.3@5085,1700 H3.3@5091,1694 5091,2135 ; v1(5090,2175) 5091,2174 5091,2136 ; 5091,2155.69 cw(c5109.31,2155.69) v1@5096.36,2168.64 ; 5091,2194.31 ccw(c5109.31,2194.31) v1@5096.36,2181.36 ; v1(6035,2825) 6036.76,2825 C11.1@6190,2978.24 ; R9.1@6035,2834 ccw(c6035,2859.98) 6053.37,2841.61 ; C9.1@6038.84,3191.16 cw(c6060.18,3169.82) 6060.18,3200 cw(c6060.18,3230.18) C9.1@6038.84,3208.84 ; R9.1@6044,2825 cw(c6061.47,2825) R9.1@6049.12,2837.36 ; C11.1@6181.16,2969.4 ccw(c6159.82,2948.06) 6159.82,2978.24 ccw(c6159.82,3008.42) C11.1@6181.16,2987.08 ; C12.1@6181.62,3240 6070,3240 C9.1@6030,3200 ; C12.1@6190,3231.62 L2.2@6270,3231.62 ; C12.1@6198.84,3222.78 cw(c6220.18,3201.44) 6220.18,3231.62 cw(c6220.18,3261.8) C12.1@6198.84,3240.46 ; L3.2@6261.16,2798.84 ccw(c6239.82,2820.18) 6270,2820.18 ccw(c6300.18,2820.18) L3.2@6278.84,2798.84 ; L2.2@6261.16,3222.78 ccw(c6239.82,3201.44) 6239.82,3231.62 ccw(c6239.82,3261.8) L2.2@6261.16,3240.46 ; L3.2@6270,2790 6270,2898.24 C11.1@6190,2978.24 ; C15.1@6270,3135 6265,3130 6160,3130 6090,3200 C9.1@6030,3200 ; C9.1@6030,3200 6080,3150 6080,3020 6121.76,2978.24 C11.1@6190,2978.24
  Bottom Layer w10: v1(4880,2235) 4871.65,2235 4871.14,2235.51 4871.14,2233.86 4930,2175 v1(5090,2175) 5110,2155 5365,2155 v1(6035,2825) ; v1@6026,2825 cw(c6004.27,2825) 6019.64,2809.64 cw(c6035,2794.27) v1@6035,2816
VDD: C3.1 C4.2 C5.2 H6.16 J1.3 P1.9 P5.1 P7.1 P9.1 R1.2 R11.1 S1.3 U1.3 U2.64 | length 12162.9
  Top Layer w10: H6.16@4442.38,1696 4425,1713.37 4425,2380 ; v3(4475,2335) 4470,2335 4425,2380 ; C5.2@4546.16,2391.16 cw(c4524.82,2369.82) 4555,2369.82 cw(c4585.18,2369.82) C5.2@4563.84,2391.16 ; C5.2@4546.16,2408.84 ccw(c4524.82,2430.18) 4555,2430.18 ccw(c4585.18,2430.18) C5.2@4563.84,2408.84 ; P5.1@4599.28,2285 4555,2329.28 C5.2@4555,2400 4555,2574.95 ; U2.64@4636.51,2656.46 4555,2574.95 ; 4425,2380 4425,2444.95 4555,2574.95
  Top Layer w20: 6265,1570 6275,1560 6640,1560 6902.89,1822.89 6902.89,3633.17 P7.1@6862.36,3673.7
  Top Layer w40: P9.1@2325,2930 P9.1@2330,2925 ; P9.1@2335,2930 2345,2920 2405,2920 R1.2@2779.29,2920 2779.29,2965.62 2845.68,3032.01 3247.01,3032.01 3321.3,3106.3 3321.3,3375 3186,3510.3 3186,3510.87 3136.77,3560.1 3409.9,3560.1 3500,3470 3500,2985 ; C4.2@2825,3560 3134.9,3560 C3.1@3135,3560.1 3218.01,3643.12 3218.01,3651.24 ; C4.2@2830,3585 2830,3695.75 2897.13,3762.87 U1.3@2897.13,3808.24 ; C3.1@3146.77,3580 3218.01,3651.24 ; S1.3@3218.01,3861 3218.01,3651.24 ; v3(3670,2335) 3629.57,2335 3500,2464.57 3500,2915 3500,2985 ; R11.1@3730,2905 3580,2905 3500,2985 ; v3(4475,2335) 4512.06,2297.94 4512.06,1869.94 4892,1490 6185,1490 6265,1570 v1(6325,1630)
  Bottom Layer w10: P1.9@6294.41,1799.41 6294.41,1660.59 v1(6325,1630)
  Bottom Layer w40: v3(3670,2335) v3(4475,2335)
VOREG: C6.1 H3.1 P6.1 U2.1 | length 1296.9
  Top Layer w10: U2.1@4718.54,2656.46 4991,2384 H3.1@4991,1694 ; C6.1@4782.71,2400 4871.73,2400 P6.1@4875.87,2404.13 ; C6.1@4791.55,2391.16 cw(c4812.89,2369.82) 4812.89,2400 cw(c4812.89,2430.18) C6.1@4791.55,2408.84 ; P6.1@4880,2400 4944.49,2400 4955,2410.51
VTP+: L1.1 P10.3 U3.1 | length 711.3
  Top Layer w10: L1.1@6270,2988.24 6308.24,2950 6353.41,2950 6516.41,3113 U3.1@6557,3113 6759.36,3113 P10.3@6857.36,3015
VTP-: L2.1 P10.1 U3.3 | length 672.7
  Top Layer w10: L2.1@6330,3231.62 6343.38,3231.62 U3.3@6462,3113
  Bottom Layer w10: U3.3@6462,3113 6462,3192 6485,3215 P10.1@6857.36,3215 P10.1@6865,3215
pads on no net: INT_EX.2@6161.05,2001.75 J1.2@6386,1631 P1.7 P1.8 P1.11 PDN.2@6161.05,2375.96 RST_N.2@5959.97,2188.17 S1.2@3217.01,3920 SCK.2@5959.97,2001.75 SCS.2@6161.05,1815.33 SDIRX.2@6161.05,1637.41 SDOTX.2@5959.97,1815.33 STATE.2@6161.05,2188.17 WAKE.2@5959.97,1637.41

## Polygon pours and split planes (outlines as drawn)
no net on Top Layer "Top Layer-No Net 1" (solid, pour order 2): 5795,2850
AVSS on Top Layer "Top Layer-No Net" (solid, remove dead copper, pour order 17): 5810,3610 5805,3605 5805,2685 6929.59,2685 6935,2690.41 6920,2705.41 6920,3610
GND on Top Layer "Top Layer-No Net" (solid, remove dead copper, pour order 19): 2270,4465 2270,1425 2285,1410 2300,1425 6930,1425 6930,4460 6925,4465
AVSS on Bottom Layer "Top Layer-No Net" (solid, remove dead copper, pour order 21): 5760,3605.71 5765.35,3600.71 6952.55,3600.71 6952.55,2705.71 6936.51,2690.71 6931.16,2685.71 5770.7,2685.71
GND on Bottom Layer "Top Layer-No Net" (solid, remove dead copper, pour order 23): 2275,4465 6930,4465 6925,4460 6925,1415 2290,1415 2270,1435

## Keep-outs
Keep-Out Layer:
  lines w10: 2255.92,1407.95 6935.92,1407.95 6935.92,4479.95 2257.92,4479.95 2257.92,1409.95

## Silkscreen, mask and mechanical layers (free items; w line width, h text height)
Top Overlay:
  drawing of 7456 lines, arcs and shapes, not listed
  text "POWER" at 2975,4355 h100
  text "Uart/IIC/SPI" at 6035,4355 h100
  text "LCD顯示屏" at 5535,4341.12 h100
  text "UART" at 6309.81,4235 h50
  text "IIC" at 6511,4235 h50
  text "SPI" at 6685,4235 h50
  text "GND" at 6660,4155 h60
  text "COM0" at 3375.2,4130 h50
  text "SEG0" at 3780,4125 h50
  text "15" at 5305,4125 h50
  text "20" at 5815,4125 h50
  text "3" at 3715,4124.4 h50
  text "5" at 4320,4124.4 h50
  text "10" at 4820,4124.4 h50
  text "RX" at 6320,4055 h60
  text "SDA" at 6485,4055 h60
  text "SDI" at 6670,4055 h60
  text "3V" at 3175,4030 h50
  text "TX" at 6325,3955 h60
  text "SDO" at 6660,3955 h60
  text "SCSB" at 6635,3855 h60
  text "Vbat" at 3175,3770 h50
  text "SCK" at 6655,3760 h60
  text "SCL" at 6480,3755 h60
  text "VDD" at 6660,3650 h60
  text "HT7530" at 2831,3629.11 h80
  text "傳感器" at 5815,3485 h100
  text "BMHB6003_V1.2" at 4665,3235.4 h47
  text "VTP-" at 6655,3200 h60
  text "2019/01/25" at 4895,3150 h80
  text "NTC+" at 6655,3095 h60
  text "2752" at 3880,3035 h60
  text "BEEP" at 3300,3025 h100
  text "VTP+" at 6655,2995 h60
  text "VDD" at 2445,2908.19 h60
  text "NTC-" at 6660,2895 h60
  text "2762" at 3875,2875 h60
  text "OCDSCK" at 2400,2805 h60
  text "OCDSDA" at 2395,2710 h60
  text "GND" at 2445,2610 h60
  text "藍牙" at 5815,2555 h100
  text "BH67F2752/62" at 4375,2485 h90
  text "VOREG" at 4945,2375 h38
  text "E_LINK" at 2285,2345 h100
  text "VDD" at 4440,2265 h38
  text "VCM" at 4935,2215 h38
  text "按鍵" at 2280,2190 h100
  text "GND" at 4439.2,2140 h38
